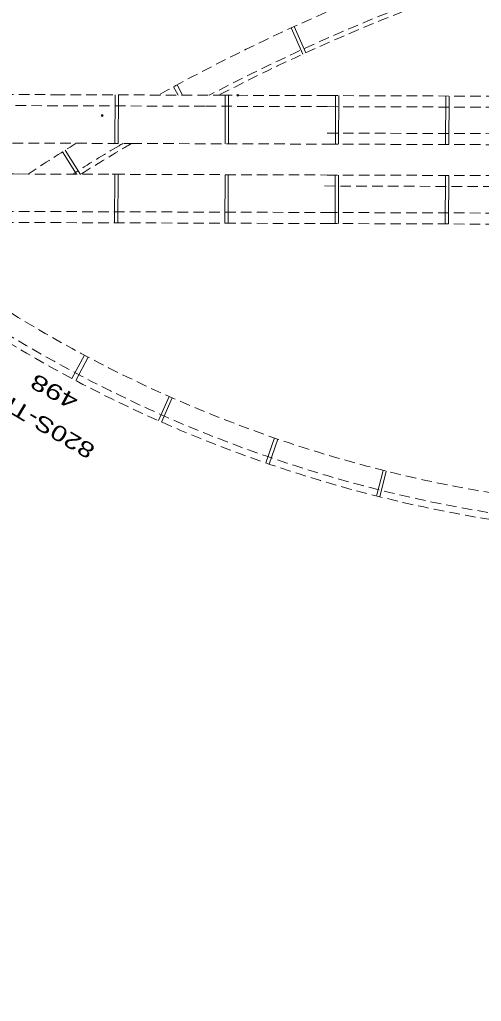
# Model space of a CAD drawing. Extents: x 2354993 to 2372084, y 6966390 to 6990057.
# Drawn here: x 2364968 to 2365387, y 6977227 to 6978118 of the extents above; entities that cross this region are included whole.
import ezdxf

# ---------------------------------------------------------------- set-up
doc = ezdxf.new("R2010")
doc.units = 0
doc.header["$LTSCALE"] = 3.2
doc.header["$PDMODE"] = 32
doc.header["$PDSIZE"] = 1.6
doc.linetypes.add('DASH_DOUBLE_DOT', pattern=[9.2, 5, -1.2, 0.3, -1.2, 0.3, -1.2])
doc.linetypes.add('MEDIUM_DASHED', pattern=[4.5, 3, -1.5])
for name, color, linetype, lineweight in [('12', 7, 'Continuous', 13), ('13', 7, 'Continuous', 13), ('17', 7, 'Continuous', 13), ('5', 7, 'Continuous', 13), ('60', 7, 'DASH_DOUBLE_DOT', 13), ('61', 7, 'Continuous', 13), ('9', 7, 'Continuous', 13)]:
    doc.layers.add(name, color=color, linetype=linetype, lineweight=lineweight)

msp = doc.modelspace()

# ---------------------------------------------------------------- linework, layer by layer
at = {"layer": '12'}
for p, q in [((2365224.948, 6978086.442), (2365214.15, 6978110.095)), ((2365227.675, 6978087.69), (2365216.877, 6978111.343)), ((2365054.48, 6978049.423), (2365054.331, 6978005.423)), ((2365057.479, 6978049.413), (2365057.331, 6978005.413)), ((2365154.48, 6978049.086), (2365154.331, 6978005.086)), ((2365157.479, 6978049.076), (2365154.48, 6978049.086)), ((2365157.479, 6978049.076), (2365157.33, 6978005.075)), ((2365254.479, 6978048.749), (2365254.331, 6978004.748)), ((2365257.479, 6978048.738), (2365257.33, 6978004.738)), ((2365354.478, 6978048.411), (2365354.33, 6978004.411)), ((2365357.477, 6978048.401), (2365357.329, 6978004.4)), ((2365054.331, 6978005.423), (2365057.331, 6978005.413)), ((2365019.476, 6977977.542), (2365006.781, 6977997.723)), ((2365023.164, 6977977.315), (2365009.318, 6977999.322)), ((2365054.237, 6977977.426), (2365051.735, 6977977.435)), ((2365054.237, 6977977.426), (2365054.088, 6977933.426)), ((2365057.236, 6977977.415), (2365057.088, 6977933.416)), ((2365154.237, 6977977.088), (2365154.088, 6977933.089)), ((2365157.236, 6977977.078), (2365157.087, 6977933.079)), ((2365254.236, 6977976.751), (2365254.088, 6977932.751)), ((2365257.236, 6977976.741), (2365257.087, 6977932.741)), ((2365354.235, 6977976.412), (2365354.087, 6977932.413)), ((2365357.234, 6977976.402), (2365357.086, 6977932.403)), ((2365157.087, 6977933.079), (2365154.088, 6977933.089)), ((2365103.591, 6977775.967), (2365093.851, 6977754.032)), ((2365106.334, 6977774.753), (2365096.595, 6977752.818)), ((2365199.176, 6977738.333), (2365191.349, 6977715.645)), ((2365202.013, 6977737.358), (2365194.186, 6977714.67)), ((2365297.64, 6977708.993), (2365291.783, 6977685.719)), ((2365300.55, 6977708.264), (2365294.693, 6977684.989))]:
    msp.add_line(p, q, dxfattribs=at)
at = {"layer": '17'}
for p, q in [((2365026.703, 6977813.423), (2365015.363, 6977792.279)), ((2365030.228, 6977811.532), (2365018.897, 6977790.405))]:
    msp.add_line(p, q, dxfattribs=at)
at = {"layer": '5', "linetype": 'MEDIUM_DASHED'}
for p, q in [((2365005.606, 6978049.588), (2364716.185, 6978050.564)), ((2365153.242, 6978049.09), (2365005.606, 6978049.589)), ((2365247.018, 6978048.774), (2365148.511, 6978049.107)), ((2365247.019, 6978048.774), (2365605.169, 6978047.567)), ((2365017.01, 6978039.548), (2364725.744, 6978040.53)), ((2365135.994, 6978039.149), (2365017.009, 6978039.549)), ((2365246.983, 6978038.773), (2365129.646, 6978039.169)), ((2364759.969, 6978006.415), (2365074.373, 6978005.355)), ((2365069.334, 6978005.372), (2365246.869, 6978004.773)), ((2365246.87, 6978004.774), (2365605.02, 6978003.566)), ((2363786.467, 6977981.699), (2365246.775, 6977976.776)), ((2365246.776, 6977976.776), (2365604.926, 6977975.568)), ((2363786.352, 6977947.7), (2365246.66, 6977942.776)), ((2365246.661, 6977942.775), (2365604.811, 6977941.567)), ((2363786.319, 6977937.7), (2365246.626, 6977932.776)), ((2365246.627, 6977932.775), (2365604.777, 6977931.568))]:
    msp.add_line(p, q, dxfattribs=at)
at = {"layer": '5'}
msp.add_line((2364790.346, 6977978.316), (2364975.778, 6977977.691), dxfattribs=at)
at = {"layer": '5', "linetype": 'MEDIUM_DASHED'}
for points in [[(2365246.984, 6978038.773), (2365605.134, 6978037.566), (2365605.134, 6978037.566)], [(2365246.903, 6978014.774), (2365605.053, 6978013.566), (2365605.053, 6978013.566)], [(2365244.474, 6977966.825), (2365602.624, 6977965.617), (2365602.624, 6977965.616)]]:
    msp.add_lwpolyline(points, dxfattribs=at)
for centre, radius, start, end in [((2365952.337, 6976500.333), 1770.947, 100.46125, 118.99651), ((2365952.338, 6976500.332), 1748.947, 99.58224, 117.67913), ((2365952.338, 6976500.332), 1744.947, 99.58224, 117.42976), ((2365952.337, 6976500.333), 1770.947, 121.79432, 123.46547), ((2365952.338, 6976500.332), 1748.947, 120.75073, 122.36718), ((2366144.618, 6976183.844), 2115.231, 120.55421, 122.00678), ((2365591.415, 6978874.774), 1226.227, 230.08464, 288.43495), ((2365591.415, 6978874.774), 1220.227, 230.42494, 288.43495), ((2365591.415, 6978874.774), 1202.227, 231.48183, 288.43495), ((2366864.416, 6975944.503), 1927.859, 114.19653, 168.16581), ((2366864.416, 6975944.503), 1923.859, 114.19652, 168.16581), ((2366864.416, 6975944.503), 1901.859, 114.19652, 168.16581)]:
    msp.add_arc(centre, radius, start, end, dxfattribs=at)
at = {"layer": '5'}
for radius, start, end in [(1748.947, 120.62099, 120.75073), (1744.947, 120.40007, 120.70834)]:
    msp.add_arc((2365952.338, 6976500.332), radius, start, end, dxfattribs=at)
at = {"layer": '60'}
msp.add_arc((2366864.416, 6975944.503), 1881.859, 114.65077, 155.69784, dxfattribs=at)
at = {"layer": '61'}
for p, q in [((2365107.638, 6978056.848), (2365111.791, 6978049.194)), ((2365110.714, 6978058.517), (2365115.727, 6978049.28))]:
    msp.add_line(p, q, dxfattribs=at)
at = {"layer": '9'}
for p in [(2365165.912, 6978049.048), (2365042.914, 6978030.655)]:
    msp.add_point(p, dxfattribs=at)

# ---------------------------------------------------------------- texts
at = {"layer": '13'}
for s, rotation, width, p in [('498', 151.573, 1.45, (2365022.526, 6977775.602)), ('820S-TF', 149.453, 1.35, (2365037.607, 6977730.626))]:
    msp.add_text(s, height=14, rotation=rotation, dxfattribs=dict(at, width=width)).set_placement(p)

doc.saveas('drawing.dxf')
